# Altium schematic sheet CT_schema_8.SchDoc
size 371 x 245 mm
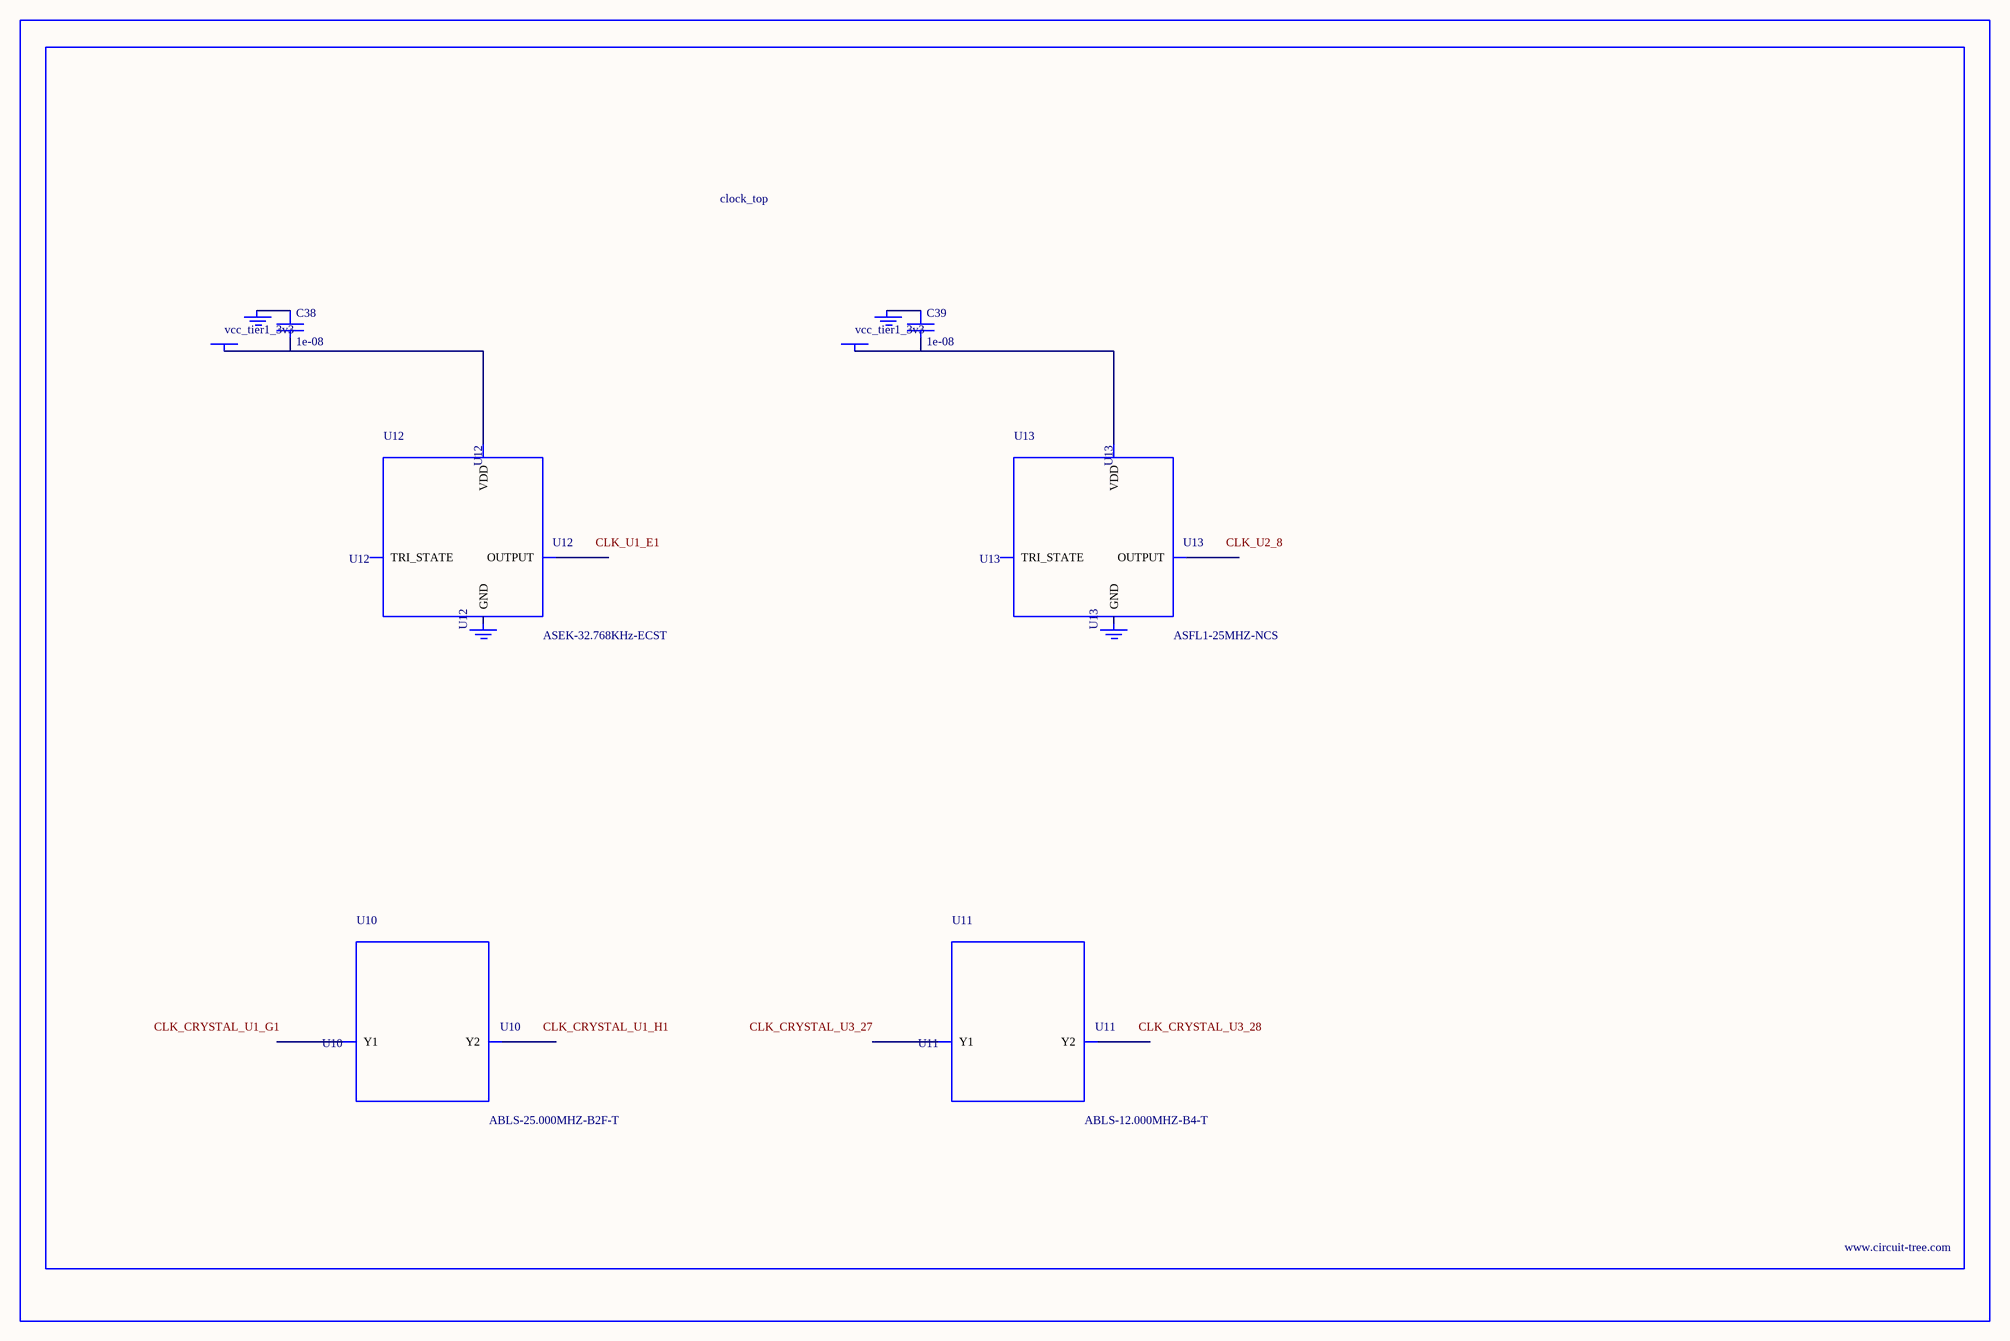
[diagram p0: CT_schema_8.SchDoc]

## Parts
BORDER7  (no value)
C38  1e-08  [C0402]
C39  1e-08  [C0402]
GND_INSTANCE_7_0  (no value)
GND_INSTANCE_7_1  (no value)
GND_INSTANCE_7_2  (no value)
GND_INSTANCE_7_3  (no value)
POWER_INSTANCE_7_0  vcc_tier1_3v3
POWER_INSTANCE_7_1  vcc_tier1_3v3
U10  ABLS-25.000MHZ-B2F-T  [ABLS-25.000MHZ-B2F-T]
U11  ABLS-12.000MHZ-B4-T  [ABLS-12.000MHZ-B4-T]
U12  ASEK-32.768KHz-ECST  [ASEK]
U13  ASFL1-25MHZ-NCS  [ASFL1]

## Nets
NetC38_1: C38.1 GND_INSTANCE_7_0.0(GND)
NetC38_2: C38.2 POWER_INSTANCE_7_0.0(PWR) U12.4(VDD)
NetC39_1: C39.1 GND_INSTANCE_7_2.0(GND)
NetC39_2: C39.2 POWER_INSTANCE_7_1.0(PWR) U13.4(VDD)

Not connected (* = marked no-connect by the designer): GND_INSTANCE_7_1 0(GND); GND_INSTANCE_7_3 0(GND); U10 1(Y1) 2(Y2); U11 1(Y1) 2(Y2); U12 1(TRI_STATE) 2(GND) 3(OUTPUT); U13 1(TRI_STATE) 2(GND) 3(OUTPUT)

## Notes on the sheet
- Labels drawn without touching a wire or pin: CLK_CRYSTAL_U1_G1, CLK_CRYSTAL_U1_H1, CLK_CRYSTAL_U3_27, CLK_CRYSTAL_U3_28, CLK_U1_E1, CLK_U2_8

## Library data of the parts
BORDER7 = BORDER_PAGE7
C38 C39 = C0402C103K3RAC
GND_INSTANCE_7_0-GND_INSTANCE_7_3 = GND
POWER_INSTANCE_7_0 POWER_INSTANCE_7_1 = PWR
